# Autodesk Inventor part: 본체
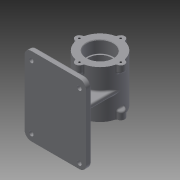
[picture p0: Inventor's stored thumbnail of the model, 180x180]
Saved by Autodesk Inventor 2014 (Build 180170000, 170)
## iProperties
Created: 2015-12
Part Number: 본체
Material: Generic
Document SubType Name: Modeling
Designer: user
Density: 1 g/cm^3
Appearance: Default
Author: user
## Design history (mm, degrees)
sketch "Sketch1"
  geometry: C1 r 37 at (0, 0); 1 further point
  constraints: 1 centre point, 1 coincident
  dimensions: "d0" = 74 diameter of C1
extrude "Extrusion1" new body sketch "Sketch1" distance "d1" = 85; taper "d2" = 0 deg
sketch "Sketch2"
  geometry: C1 r 7 at (0, 37); 1 further point
  constraints: 1 centre point, 1 vertical alignment, 1 other
  dimensions: "d3" = 14 diameter of C1
extrude "Extrusion2" join sketch "Sketch2" distance "d4" = 15; taper "d5" = 0 deg
pattern_circular "Circular Pattern1" dims angle "d7" = 360 deg
sketch "Sketch3"
  geometry: C1 r 7 at (0, 37); A1 r 37 centre (0, 0) between (0, 37) and (-36.338, 6.969) reference; A2 r 7 centre (-37, 0) between (-36.338, 6.969) and (-36.338, -6.969) reference
  constraints: 1 centre point, 1 point on circle
  dimensions: "d9" = 14 diameter of C1
extrude "Extrusion3" join sketch "Sketch3" distance "d10" = 15; taper "d11" = 0 deg
pattern_circular "Circular Pattern2" dims angle "d13" = 360 deg
sketch "Sketch4"
  geometry: L1 (37, 70)-(46.125, 73.321); L2 (37, 15)-(49.525, 10.441); L3 (37, 15)-(37, 70); L4 (49.525, 10.441)-(46.125, 73.321); L5 (0, 0)-(0, -15.409); 1 further point
  constraints: 10 end point
revolve "Revolution1" sketch "Sketch4" stored, may be unused: angle "d15" = 90 deg
sketch "Sketch5"
  geometry: L1 (0, 0)-(-70, 0); L2 (44, 0)-(36.338, 0) reference; L3 (36.338, 85)-(44, 85) reference; L4 (-70, 17.5)-(-70, 67.5); L5 (0, 0)-(0, 42.5); L6 (-70, 17.5)-(-21.498, 23.455); L7 (-70, 67.5)-(-18.24, 61.145); L8 (-21.498, 23.455)-(-18.24, 61.145)
  constraints: 12 end point
  dimensions: "d16" = 70 distance of L1.start L1.end; "d17" = 50 distance of L4.start L4.end; "d18" = 42.5 distance of L1.start L5.end; "d19" = 25 vertical distance of L4.start L5.end; "d20" = 83 deg angle of L4 L6; "d21" = 97 deg angle of L4 L7
extrude "Extrusion4" join sketch "Sketch5" stored distance "d22" = 12; taper "d23" = 0 deg
workplane "Work Plane1"
sketch "Sketch6"
  geometry: L1 (-6, -70)-(6, -70) reference; L2 (37, -70)-(-37, -70); L3 (-37, -70)-(-37, 0); L4 (-37, 0)-(37, 0); L5 (37, 0)-(37, -70); 1 further point
  constraints: 8 end point
  dimensions: "d24" = 74 distance of L2.start L2.end; "d25" = 0 distance between parallel lines of L2 L1; "d26" = 37 horizontal distance of point (0, 0) L2.end
extrude "Extrusion5" join sketch "Sketch6" stored distance "d27" = 8; taper "d28" = 0 deg
sketch "Sketch7"
  geometry: L1 (12, 0)-(12, -21) reference; L2 (-31, -21)-(0, -21) reference; L3 (-49, -105)-(61, -105); L4 (61, -105)-(61, 35); L5 (61, 35)-(-49, 35); L6 (-49, 35)-(-49, -105); 1 further point
  constraints: 8 end point
  dimensions: "d29" = 110 distance of L4.end L5.end; "d30" = 140 distance of L5.end L3.start; "d31" = 84 distance between parallel lines of L2 L3; "d32" = 61 distance between parallel lines of L1 L6
extrude "Extrusion6" join sketch "Sketch7" distance "d33" = 10; taper "d34" = 0 deg
hole "Hole1" diameter "d37" = 3.459; stored, may be unused: countersink angle "d41" = 90 deg, drill point angle "d43" = 118 deg; dims "d35" = 10, "d36" = 10, "d38" = 9, "d39" = 47, "d40" = 22, "d42" = 11
pattern_circular "Circular Pattern3" dims angle "d45" = 360 deg
hole "Hole2" diameter "d49" = 3.459; stored, may be unused: countersink angle "d53" = 90 deg, drill point angle "d55" = 118 deg; dims "d47" = 10, "d48" = 10, "d50" = 9, "d51" = 47, "d52" = 22, "d54" = 11
pattern_circular "Circular Pattern4" dims angle "d57" = 360 deg
sketch "Sketch8"
  geometry: L1 (-49, -105)-(61, -105) reference; L2 (-49, 35)-(-49, -105) reference; C1 r 4 at (-37, -93); C2 r 4 at (-37, 20.386); C3 r 4 at (48.96, -95.614); C4 r 4 at (48.96, 20.386); 1 further point
  constraints: 4 centre point
  dimensions: "d59" = 8 diameter of C1; "d60" = 8 diameter of C2; "d61" = 8 diameter of C3; "d62" = 8 diameter of C4; "d63" = 86 distance of C3.centre C1.centre; "d64" = 116 distance of C4.centre C3.centre; "d65" = 0 horizontal distance of C3.centre C4.centre; "d66" = 0 horizontal distance of C1.centre C2.centre; "d67" = 0 vertical distance of C4.centre C2.centre; "d68" = 12 distance from line of L2 C1.centre; "d69" = 12 distance from line of L1 C1.centre
extrude "Extrusion7" cut sketch "Sketch8" distance "d70" = 10; taper "d71" = 0 deg
hole "Hole3" diameter "d74" = 42; stored, may be unused: countersink angle "d78" = 90 deg, drill point angle "d80" = 0 deg; dims "d72" = 10, "d73" = 10, "d75" = 9, "d76" = 47, "d77" = 22, "d79" = 63
hole "Hole4" diameter "d83" = 47; stored, may be unused: countersink angle "d87" = 90 deg, drill point angle "d89" = 0 deg; dims "d81" = 10, "d82" = 10, "d84" = 9, "d85" = 47, "d86" = 22, "d88" = 22
fillet "Fillet1" dims "d90" = 12
fillet "Fillet2" dims "d91" = 0.3
chamfer "Chamfer1" distance "d92" = 1; stored, may be unused: second distance "d93" = 2, angle "d94" = 45 deg
fillet "Fillet3" dims "d95" = 3
pattern_circular "Circular Pattern5" dims angle "d97" = 360 deg
fillet "Fillet4" dims "d99" = 3
pattern_circular "Circular Pattern6" dims angle "d101" = 360 deg
fillet "Fillet5" dims "d103" = 3
fillet "Fillet6" dims "d104" = 3
fillet "Fillet7" dims "d105" = 3
fillet "Fillet8" dims "d106" = 3
body "Solid1"
